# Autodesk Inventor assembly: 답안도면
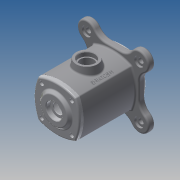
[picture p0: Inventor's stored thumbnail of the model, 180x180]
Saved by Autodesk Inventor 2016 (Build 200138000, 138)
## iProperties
Created: 2016-05
Part Number: 답안도면
Document SubType Name: Assembly
Designer: Administrator
Author: Administrator
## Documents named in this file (3)
- D:\460508V1004\답안도면.iam
- D:\460508V1004\본체.ipt
- D:\460508V1004\커버.ipt
